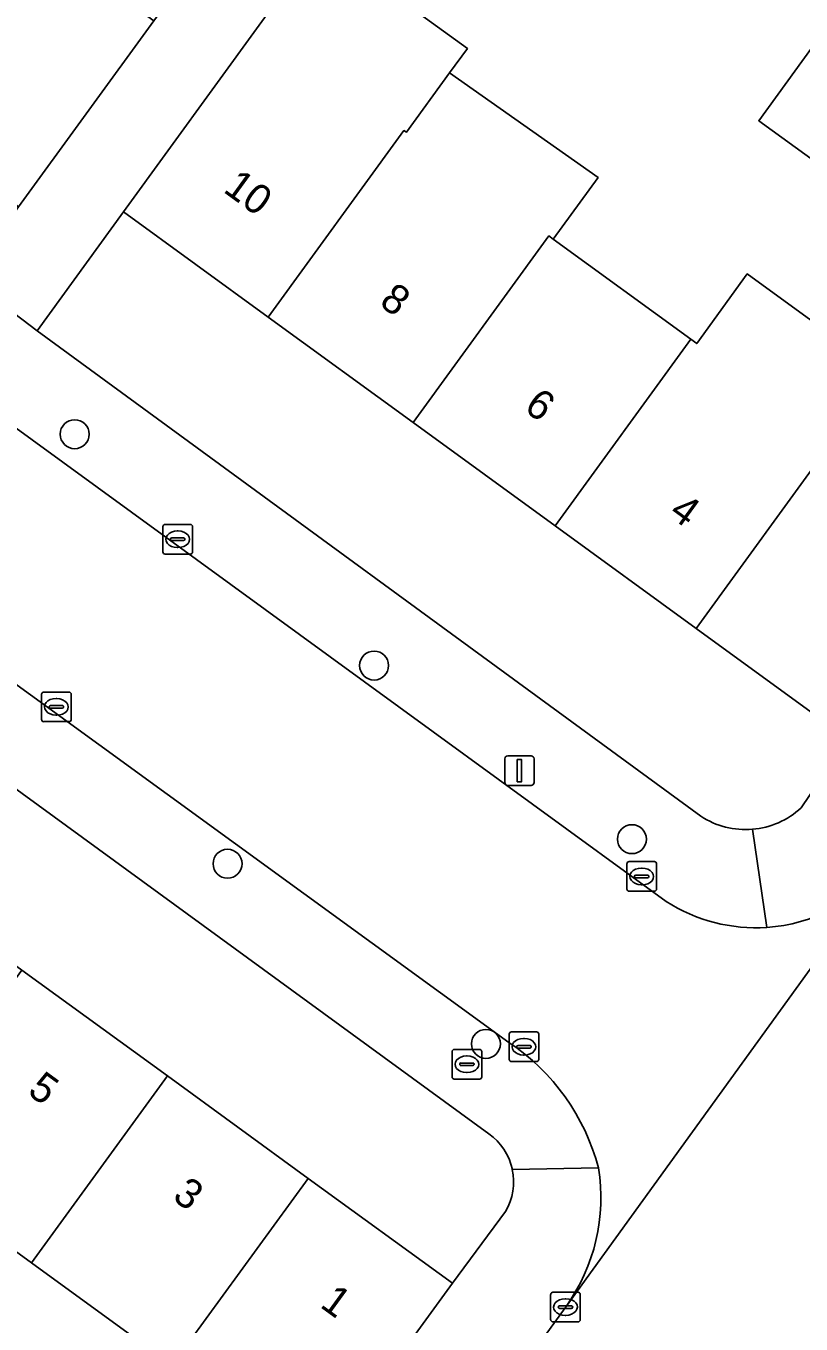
# Model space of a CAD drawing. Extents: x 159674 to 160531, y 382172 to 382904.
# Drawn here: x 160224.11 to 160250.27, y 382538.52 to 382582.33 of the extents above; entities that cross this region are included whole.
import ezdxf

# ---------------------------------------------------------------- set-up
doc = ezdxf.new("R2010")
doc.units = 0
for name, color, linetype in [('IMGEO_Boom', 7, 'Continuous'), ('IMGEO_Brandkraan', 7, 'Continuous'), ('IMGEO_Erf', 7, 'Continuous'), ('IMGEO_Kolk', 7, 'Continuous'), ('IMGEO_Lichtmast', 7, 'Continuous'), ('IMGEO_Pand', 7, 'Continuous'), ('IMGEO_Pand_nummerreeks', 7, 'Continuous'), ('IMGEO_Rijbaan_lokaal_gesloten', 7, 'Continuous'), ('IMGEO_Rijbaan_lokaal_open', 7, 'Continuous'), ('IMGEO_Voetpad_open', 7, 'Continuous')]:
    doc.layers.add(name, color=color, linetype=linetype)

msp = doc.modelspace()

# ---------------------------------------------------------------- linework, layer by layer
at = {"layer": 'IMGEO_Boom'}
for centre in [(160225.751, 382568.553), (160235.859, 382560.746), (160244.564, 382554.886), (160230.912, 382554.058), (160239.635, 382547.977)]:
    msp.add_circle(centre, 0.489, dxfattribs=at)
at = {"layer": 'IMGEO_Brandkraan'}
for p, q in [((160238.492, 382546.863), (160238.492, 382547.715)), ((160238.567, 382547.789), (160239.419, 382547.789)), ((160239.493, 382547.715), (160239.493, 382546.863)), ((160238.751, 382547.283), (160238.751, 382547.295)), ((160239.189, 382547.246), (160238.791, 382547.246)), ((160238.794, 382547.332), (160239.192, 382547.332)), ((160238.98, 382547.569), (160239.005, 382547.569)), ((160239.235, 382547.295), (160239.235, 382547.283)), ((160239.419, 382546.789), (160238.567, 382546.789)), ((160239.003, 382547.009), (160238.978, 382547.009))]:
    msp.add_line(p, q, dxfattribs=at)
for points in [[(160238.492, 382546.863), (160238.492, 382547.715)], [(160238.567, 382547.789), (160239.419, 382547.789)], [(160239.493, 382547.715), (160239.493, 382546.863)], [(160239.419, 382546.789), (160238.567, 382546.789)]]:
    msp.add_lwpolyline(points, dxfattribs=at)
for centre, radius, start, end in [((160238.569, 382547.713), 0.0765, 91.552, 178.448), ((160238.569, 382547.713), 0.0765, 91.552, 178.448), ((160239.417, 382547.713), 0.0765, 1.552, 88.448), ((160239.417, 382547.713), 0.0765, 1.552, 88.448), ((160238.791, 382547.292), 0.0403, 85.8775, 175.7526), ((160238.788, 382547.282), 0.0366, 178.938, 274.7102), ((160239.192, 382547.289), 0.043, 264.8664, 352.4533), ((160239.196, 382547.294), 0.0386, 1.7309, 96.639), ((160238.569, 382546.865), 0.0765, 181.552, 268.448), ((160238.569, 382546.865), 0.0765, 181.552, 268.448), ((160239.417, 382546.865), 0.0765, 271.552, 358.448), ((160239.417, 382546.865), 0.0765, 271.552, 358.448)]:
    msp.add_arc(centre, radius, start, end, dxfattribs=at)
for centre, major_axis, ratio, start_param, end_param in [((160238.979, 382547.289), (-0.387, 0.002), 0.722429, 4.712389, 7.853982), ((160239.004, 382547.289), (-0.39, 0.002), 0.717154, 1.570796, 4.712389)]:
    msp.add_ellipse(centre, major_axis=major_axis, ratio=ratio, start_param=start_param, end_param=end_param, dxfattribs=at)
at = {"layer": 'IMGEO_Erf'}
for points in [[(160248.843, 382579.132), (160251.284, 382582.484), (160245.602, 382586.613), (160243.161, 382583.261), (160241.166, 382584.714), (160239.162, 382586.173), (160241.603, 382589.525), (160238.707, 382591.628), (160234.032, 382585.187), (160239.007, 382581.569), (160238.409, 382580.747), (160243.42, 382577.213), (160241.909, 382575.136), (160246.549, 382571.761), (160246.751, 382571.614), (160248.457, 382573.961), (160253.249, 382570.477), (160251.542, 382568.129), (160256.431, 382564.573)], [(160257.726, 382564.695), (160261.372, 382569.812), (160260.709, 382570.329), (160255.701, 382573.975), (160258.248, 382577.474), (160255.283, 382579.572), (160252.842, 382576.22), (160250.847, 382577.673), (160248.843, 382579.132)], [(160237.179, 382568.945), (160232.288, 382572.503), (160227.395, 382576.062), (160224.48, 382572.038), (160246.891, 382555.658)], [(160250.273, 382555.941), (160251.85, 382558.275), (160246.728, 382562), (160241.969, 382565.462), (160237.179, 382568.945)], [(160216.898, 382561.575), (160214.042, 382557.69), (160219.236, 382553.912), (160223.969, 382550.469), (160228.884, 382546.895), (160233.636, 382543.439), (160238.502, 382539.899), (160240.295, 382542.32)], [(160239.728, 382544.943), (160216.898, 382561.575)], [(160229.047, 382537.13), (160224.295, 382540.586), (160219.38, 382544.16), (160217.267, 382541.345), (160212.578, 382544.777), (160214.647, 382547.603), (160209.453, 382551.381), (160202.472, 382541.785), (160205.407, 382539.65), (160207.895, 382543.071), (160210.155, 382541.427), (160211.914, 382540.148), (160209.426, 382536.727), (160215.055, 382532.633), (160217.543, 382536.054), (160219.803, 382534.41), (160221.562, 382533.131), (160219.074, 382529.71), (160221.967, 382527.617), (160224.461, 382531.045), (160226.154, 382529.799), (160229.46, 382527.365), (160230.277, 382526.771), (160234.204, 382532.209)]]:
    msp.add_lwpolyline(points, dxfattribs=at)
for centre, radius, start, end in [((160248.4, 382557.973), 2.764, 274.8002, 312.6707), ((160248.399, 382557.966), 2.756, 236.8423, 274.8374), ((160238.59, 382543.321), 1.982, 12.3047, 54.9431), ((160238.595, 382543.326), 1.975, 329.3782, 12.1807)]:
    msp.add_arc(centre, radius, start, end, dxfattribs=at)
at = {"layer": 'IMGEO_Kolk'}
for p, q in [((160228.728, 382564.582), (160228.728, 382565.434)), ((160228.803, 382565.508), (160229.655, 382565.508)), ((160229.216, 382565.288), (160229.241, 382565.288)), ((160229.729, 382565.434), (160229.729, 382564.582)), ((160228.987, 382565.002), (160228.987, 382565.014)), ((160229.425, 382564.965), (160229.027, 382564.965)), ((160229.03, 382565.051), (160229.428, 382565.051)), ((160229.239, 382564.728), (160229.214, 382564.728)), ((160229.471, 382565.014), (160229.471, 382565.002)), ((160229.655, 382564.508), (160228.803, 382564.508)), ((160224.634, 382558.926), (160224.634, 382559.778)), ((160224.709, 382559.852), (160225.561, 382559.852)), ((160225.122, 382559.632), (160225.147, 382559.632)), ((160225.635, 382559.778), (160225.635, 382558.926)), ((160224.893, 382559.346), (160224.893, 382559.358)), ((160225.331, 382559.309), (160224.933, 382559.309)), ((160224.936, 382559.395), (160225.334, 382559.395)), ((160225.145, 382559.072), (160225.12, 382559.072)), ((160225.377, 382559.358), (160225.377, 382559.346)), ((160225.561, 382558.852), (160224.709, 382558.852)), ((160244.394, 382553.201), (160244.394, 382554.053)), ((160244.469, 382554.127), (160245.321, 382554.127)), ((160244.882, 382553.907), (160244.907, 382553.907)), ((160245.395, 382554.053), (160245.395, 382553.201)), ((160244.653, 382553.621), (160244.653, 382553.633)), ((160245.091, 382553.584), (160244.693, 382553.584)), ((160244.696, 382553.67), (160245.094, 382553.67)), ((160244.905, 382553.347), (160244.88, 382553.347)), ((160245.137, 382553.633), (160245.137, 382553.621)), ((160245.321, 382553.127), (160244.469, 382553.127)), ((160240.418, 382547.453), (160240.418, 382548.305)), ((160240.493, 382548.379), (160241.345, 382548.379)), ((160240.906, 382548.159), (160240.931, 382548.159)), ((160241.419, 382548.305), (160241.419, 382547.453)), ((160240.677, 382547.873), (160240.677, 382547.885)), ((160241.115, 382547.836), (160240.717, 382547.836)), ((160240.72, 382547.922), (160241.118, 382547.922)), ((160241.161, 382547.885), (160241.161, 382547.873)), ((160241.345, 382547.379), (160240.493, 382547.379)), ((160240.929, 382547.599), (160240.904, 382547.599)), ((160241.82, 382538.669), (160241.82, 382539.521)), ((160241.895, 382539.595), (160242.747, 382539.595)), ((160242.308, 382539.375), (160242.333, 382539.375)), ((160242.821, 382539.521), (160242.821, 382538.669)), ((160242.079, 382539.089), (160242.079, 382539.101)), ((160242.517, 382539.052), (160242.119, 382539.052)), ((160242.122, 382539.138), (160242.52, 382539.138)), ((160242.563, 382539.101), (160242.563, 382539.089)), ((160242.747, 382538.595), (160241.895, 382538.595)), ((160242.331, 382538.815), (160242.306, 382538.815))]:
    msp.add_line(p, q, dxfattribs=at)
for points in [[(160228.728, 382564.582), (160228.728, 382565.434)], [(160228.803, 382565.508), (160229.655, 382565.508)], [(160229.729, 382565.434), (160229.729, 382564.582)], [(160229.655, 382564.508), (160228.803, 382564.508)], [(160224.634, 382558.926), (160224.634, 382559.778)], [(160224.709, 382559.852), (160225.561, 382559.852)], [(160225.635, 382559.778), (160225.635, 382558.926)], [(160225.561, 382558.852), (160224.709, 382558.852)], [(160244.394, 382553.201), (160244.394, 382554.053)], [(160244.469, 382554.127), (160245.321, 382554.127)], [(160245.395, 382554.053), (160245.395, 382553.201)], [(160245.321, 382553.127), (160244.469, 382553.127)], [(160240.418, 382547.453), (160240.418, 382548.305)], [(160240.493, 382548.379), (160241.345, 382548.379)], [(160241.419, 382548.305), (160241.419, 382547.453)], [(160241.345, 382547.379), (160240.493, 382547.379)], [(160241.82, 382538.669), (160241.82, 382539.521)], [(160241.895, 382539.595), (160242.747, 382539.595)], [(160242.821, 382539.521), (160242.821, 382538.669)], [(160242.747, 382538.595), (160241.895, 382538.595)]]:
    msp.add_lwpolyline(points, dxfattribs=at)
for centre, radius, start, end in [((160228.805, 382565.432), 0.0765, 91.552, 178.448), ((160228.805, 382565.432), 0.0765, 91.552, 178.448), ((160229.653, 382565.432), 0.0765, 1.552, 88.448), ((160229.653, 382565.432), 0.0765, 1.552, 88.448), ((160229.027, 382565.011), 0.0403, 85.8775, 175.7526), ((160229.024, 382565.001), 0.0366, 178.938, 274.7102), ((160229.428, 382565.008), 0.043, 264.8664, 352.4533), ((160229.432, 382565.013), 0.0386, 1.7309, 96.639), ((160228.805, 382564.584), 0.0765, 181.552, 268.448), ((160228.805, 382564.584), 0.0765, 181.552, 268.448), ((160229.653, 382564.584), 0.0765, 271.552, 358.448), ((160229.653, 382564.584), 0.0765, 271.552, 358.448), ((160224.711, 382559.776), 0.0765, 91.552, 178.448), ((160224.711, 382559.776), 0.0765, 91.552, 178.448), ((160225.559, 382559.776), 0.0765, 1.552, 88.448), ((160225.559, 382559.776), 0.0765, 1.552, 88.448), ((160224.933, 382559.355), 0.0403, 85.8775, 175.7526), ((160224.93, 382559.345), 0.0366, 178.938, 274.7102), ((160225.334, 382559.352), 0.043, 264.8664, 352.4533), ((160225.338, 382559.357), 0.0386, 1.7309, 96.639), ((160224.711, 382558.928), 0.0765, 181.552, 268.448), ((160224.711, 382558.928), 0.0765, 181.552, 268.448), ((160225.559, 382558.928), 0.0765, 271.552, 358.448), ((160225.559, 382558.928), 0.0765, 271.552, 358.448), ((160244.471, 382554.051), 0.0765, 91.552, 178.448), ((160244.471, 382554.051), 0.0765, 91.552, 178.448), ((160245.319, 382554.051), 0.0765, 1.552, 88.448), ((160245.319, 382554.051), 0.0765, 1.552, 88.448), ((160244.693, 382553.63), 0.0403, 85.8775, 175.7526), ((160244.69, 382553.62), 0.0366, 178.938, 274.7102), ((160245.094, 382553.627), 0.043, 264.8664, 352.4533), ((160245.098, 382553.632), 0.0386, 1.7309, 96.639), ((160244.471, 382553.203), 0.0765, 181.552, 268.448), ((160244.471, 382553.203), 0.0765, 181.552, 268.448), ((160245.319, 382553.203), 0.0765, 271.552, 358.448), ((160245.319, 382553.203), 0.0765, 271.552, 358.448), ((160240.495, 382548.303), 0.0765, 91.552, 178.448), ((160240.495, 382548.303), 0.0765, 91.552, 178.448), ((160241.343, 382548.303), 0.0765, 1.552, 88.448), ((160241.343, 382548.303), 0.0765, 1.552, 88.448), ((160240.717, 382547.882), 0.0403, 85.8775, 175.7526), ((160240.714, 382547.872), 0.0366, 178.938, 274.7102), ((160241.118, 382547.879), 0.043, 264.8664, 352.4533), ((160241.122, 382547.884), 0.0386, 1.7309, 96.639), ((160240.495, 382547.455), 0.0765, 181.552, 268.448), ((160240.495, 382547.455), 0.0765, 181.552, 268.448), ((160241.343, 382547.455), 0.0765, 271.552, 358.448), ((160241.343, 382547.455), 0.0765, 271.552, 358.448), ((160241.897, 382539.519), 0.0765, 91.552, 178.448), ((160241.897, 382539.519), 0.0765, 91.552, 178.448), ((160242.745, 382539.519), 0.0765, 1.552, 88.448), ((160242.745, 382539.519), 0.0765, 1.552, 88.448), ((160242.119, 382539.098), 0.0403, 85.8775, 175.7526), ((160242.116, 382539.088), 0.0366, 178.938, 274.7102), ((160242.52, 382539.095), 0.043, 264.8664, 352.4533), ((160242.524, 382539.1), 0.0386, 1.7309, 96.639), ((160241.897, 382538.671), 0.0765, 181.552, 268.448), ((160241.897, 382538.671), 0.0765, 181.552, 268.448), ((160242.745, 382538.671), 0.0765, 271.552, 358.448), ((160242.745, 382538.671), 0.0765, 271.552, 358.448)]:
    msp.add_arc(centre, radius, start, end, dxfattribs=at)
for centre, major_axis, ratio, start_param, end_param in [((160229.215, 382565.008), (-0.387, 0.002), 0.722429, 4.712389, 7.853982), ((160229.24, 382565.008), (-0.39, 0.002), 0.717154, 1.570796, 4.712389), ((160225.121, 382559.352), (-0.387, 0.002), 0.722429, 4.712389, 7.853982), ((160225.146, 382559.352), (-0.39, 0.002), 0.717154, 1.570796, 4.712389), ((160244.881, 382553.627), (-0.387, 0.002), 0.722429, 4.712389, 7.853982), ((160244.906, 382553.627), (-0.39, 0.002), 0.717154, 1.570796, 4.712389), ((160240.905, 382547.879), (-0.387, 0.002), 0.722429, 4.712389, 7.853982), ((160240.93, 382547.879), (-0.39, 0.002), 0.717154, 1.570796, 4.712389), ((160242.307, 382539.095), (-0.387, 0.002), 0.722429, 4.712389, 7.853982), ((160242.332, 382539.095), (-0.39, 0.002), 0.717154, 1.570796, 4.712389)]:
    msp.add_ellipse(centre, major_axis=major_axis, ratio=ratio, start_param=start_param, end_param=end_param, dxfattribs=at)
at = {"layer": 'IMGEO_Lichtmast'}
for p, q in [((160240.371, 382557.699), (160241.161, 382557.699)), ((160241.161, 382557.699), (160240.371, 382557.699)), ((160240.271, 382556.799), (160240.271, 382557.599)), ((160240.271, 382557.599), (160240.271, 382556.799)), ((160241.261, 382557.599), (160241.261, 382556.799)), ((160241.261, 382556.799), (160241.261, 382557.599)), ((160241.161, 382556.699), (160240.371, 382556.699)), ((160240.371, 382556.699), (160241.161, 382556.699))]:
    msp.add_line(p, q, dxfattribs=at)
msp.add_lwpolyline([(160240.691, 382557.574), (160240.841, 382557.574), (160240.841, 382556.824), (160240.691, 382556.824), (160240.691, 382557.574)], dxfattribs=at)
for centre, start, end in [((160240.371, 382557.599), 90, 180), ((160240.371, 382557.599), 90, 180), ((160241.161, 382557.599), 0, 90), ((160241.161, 382557.599), 360, 90), ((160240.371, 382556.799), 180, 270), ((160240.371, 382556.799), 180, 270), ((160241.161, 382556.799), 270, 0), ((160241.161, 382556.799), 270, 0)]:
    msp.add_arc(centre, 0.1, start, end, dxfattribs=at)
at = {"layer": 'IMGEO_Pand'}
for points in [[(160223.426, 382586.14), (160218.859, 382579.861), (160223.859, 382576.224), (160228.427, 382582.503), (160224.383, 382585.444)], [(160236.868, 382578.802), (160236.951, 382578.742), (160238.409, 382580.747), (160239.007, 382581.569), (160234.032, 382585.187), (160231.976, 382582.36), (160227.395, 382576.062), (160232.288, 382572.503)], [(160253.286, 382581.026), (160251.284, 382582.484), (160248.843, 382579.132), (160250.847, 382577.673)], [(160241.76, 382575.244), (160241.909, 382575.136), (160243.42, 382577.213), (160238.409, 382580.747), (160236.951, 382578.742), (160236.868, 382578.802), (160232.288, 382572.503), (160237.179, 382568.945)], [(160246.549, 382571.761), (160241.909, 382575.136), (160241.76, 382575.244), (160237.179, 382568.945), (160241.969, 382565.462)], [(160251.309, 382568.299), (160251.542, 382568.129), (160253.249, 382570.477), (160248.457, 382573.961), (160246.751, 382571.614), (160246.549, 382571.761), (160241.969, 382565.462), (160246.728, 382562)], [(160256.431, 382564.573), (160251.542, 382568.129), (160251.309, 382568.299), (160246.728, 382562), (160251.85, 382558.275)], [(160219.38, 382544.16), (160224.295, 382540.586), (160228.884, 382546.895), (160223.969, 382550.469)], [(160233.636, 382543.439), (160228.884, 382546.895), (160224.295, 382540.586), (160229.047, 382537.13)], [(160233.636, 382543.439), (160229.047, 382537.13), (160233.913, 382533.59), (160238.502, 382539.899)]]:
    msp.add_lwpolyline(points, close=True, dxfattribs=at)
at = {"layer": 'IMGEO_Rijbaan_lokaal_gesloten'}
msp.add_lwpolyline([(160315.311, 382639.622), (160304.717, 382625.008), (160302.639, 382622.143), (160290.62, 382605.563), (160279.709, 382590.612), (160279.414, 382590.208), (160269.482, 382576.534), (160263.507, 382568.309), (160253.466, 382554.485), (160253.079, 382553.951), (160242.339, 382539.119), (160232.376, 382525.365), (160226.58, 382517.362), (160218.061, 382505.6), (160216.652, 382503.655), (160216.208, 382503.063), (160216.121, 382502.946), (160214.024, 382500), (160205.773, 382488.409), (160195.682, 382474.429), (160187.988, 382463.77), (160179.328, 382451.773), (160168.227, 382436.541)], dxfattribs=at)
at = {"layer": 'IMGEO_Rijbaan_lokaal_open'}
for points in [[(160140.763, 382629.192), (160140.555, 382629.351), (160136.439, 382623.587), (160136.712, 382623.379), (160240.412, 382548.029)], [(160245.716, 382552.786), (160140.763, 382629.192)], [(160242.339, 382539.119), (160253.079, 382553.951)]]:
    msp.add_lwpolyline(points, dxfattribs=at)
for centre, radius, start, end in [((160248.746, 382557.494), 5.597, 273.8234, 320.733), ((160248.746, 382557.503), 5.607, 237.285, 273.8121), ((160236.311, 382541.905), 7.37, 14.8164, 56.1899), ((160237.222, 382542.785), 6.295, 324.3819, 9.1849)]:
    msp.add_arc(centre, radius, start, end, dxfattribs=at)
at = {"layer": 'IMGEO_Voetpad_open'}
for points in [[(160140.555, 382629.351), (160140.763, 382629.192), (160245.716, 382552.786)], [(160240.412, 382548.029), (160136.712, 382623.379)], [(160158.66, 382605.256), (160215.141, 382564.235), (160214.457, 382563.306), (160216.898, 382561.575), (160239.728, 382544.943)], [(160246.891, 382555.658), (160224.48, 382572.038), (160222.117, 382573.829)], [(160249.119, 382551.909), (160248.631, 382555.219)], [(160248.631, 382555.219), (160249.119, 382551.909)], [(160243.436, 382543.79), (160240.526, 382543.743)], [(160240.526, 382543.743), (160243.436, 382543.79)], [(160240.295, 382542.32), (160238.502, 382539.899), (160233.913, 382533.59), (160234.164, 382533.388)], [(160234.204, 382532.209), (160230.277, 382526.771), (160232.376, 382525.365), (160242.339, 382539.119)]]:
    msp.add_lwpolyline(points, dxfattribs=at)
msp.add_lwpolyline([(160244.707, 382599.903), (160246.587, 382602.485), (160251.138, 382608.735), (160253.992, 382612.685), (160251.643, 382614.384), (160249.985, 382612.12), (160245.379, 382605.794), (160237.235, 382594.604), (160236.364, 382593.408), (160228.427, 382582.503), (160223.859, 382576.224), (160222.117, 382573.829), (160224.48, 382572.038), (160227.395, 382576.062), (160231.976, 382582.36), (160234.032, 382585.187), (160238.707, 382591.628), (160239.649, 382592.926)], close=True, dxfattribs=at)
for centre, radius, start, end in [((160248.4, 382557.973), 2.764, 274.8002, 312.6707), ((160248.399, 382557.966), 2.756, 236.8423, 274.8374), ((160248.746, 382557.494), 5.597, 273.8234, 320.733), ((160248.746, 382557.503), 5.607, 237.285, 273.8121), ((160236.311, 382541.905), 7.37, 14.8164, 56.1899), ((160238.59, 382543.321), 1.982, 12.3047, 54.9431), ((160238.595, 382543.326), 1.975, 329.3782, 12.1807), ((160237.222, 382542.785), 6.295, 324.3819, 9.1849)]:
    msp.add_arc(centre, radius, start, end, dxfattribs=at)

# ---------------------------------------------------------------- texts
at = {"layer": 'IMGEO_Pand_nummerreeks'}
for s, rotation, p in [('10', 323.9724, (160230.73, 382576.753)), ('8', 323.9724, (160235.994, 382572.924)), ('6', 323.9724, (160240.881, 382569.369)), ('4', 323.9724, (160245.772, 382565.811)), ('5', 323.9697, (160224.119, 382546.303)), ('3', 323.9697, (160229.011, 382542.745)), ('1', 323.9697, (160233.996, 382539.12))]:
    msp.add_text(s, height=1, rotation=rotation, dxfattribs=at).set_placement(p)

doc.saveas('drawing.dxf')
